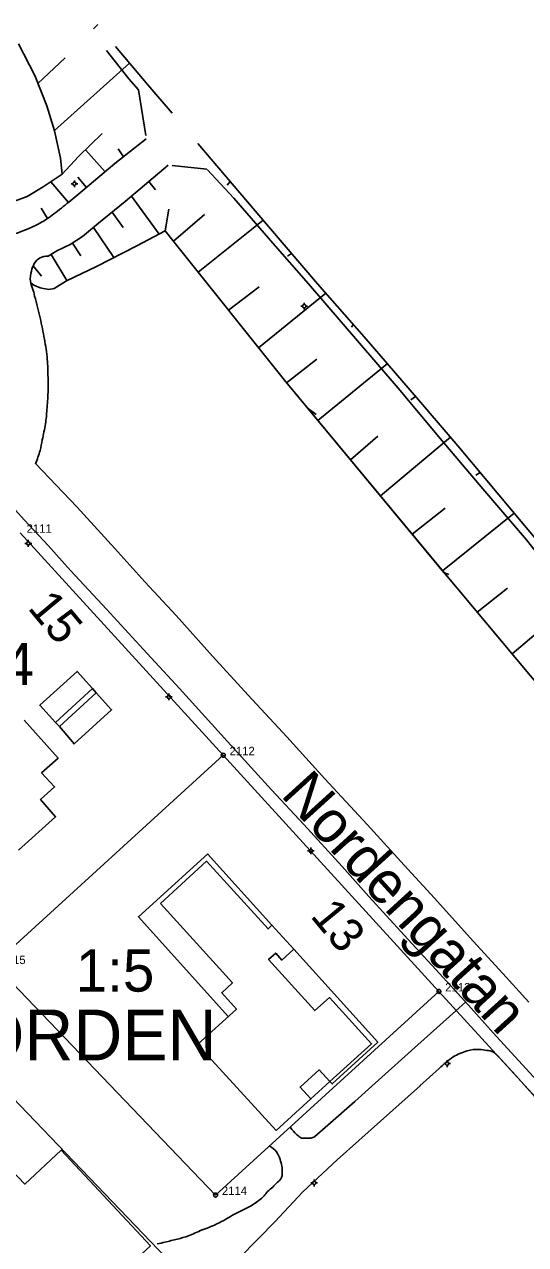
# Model space of a CAD drawing. Extents: x 1517693 to 1518189, y 6494860 to 6495280.
# Drawn here: x 1518024.6 to 1518083.9, y 6495135.7 to 6495280.1 of the extents above; entities that cross this region are included whole.
import ezdxf

# ---------------------------------------------------------------- set-up
doc = ezdxf.new("R2010")
doc.units = 0
for name, color, linetype in [('adress', 7, 'Continuous'), ('bostadshus', 7, 'Continuous'), ('fastighetsbeteckning', 7, 'Continuous'), ('gatunamn', 7, 'Continuous'), ('gc_vag', 7, 'Continuous'), ('grans', 7, 'Continuous'), ('granspunkt', 7, 'Continuous'), ('granspunkt_text', 7, 'Continuous'), ('kvartersgrans', 7, 'Continuous'), ('kvartersgrans_utan_fastgr', 7, 'Continuous'), ('kvartersnamn', 7, 'Continuous'), ('skarmtak', 7, 'Continuous'), ('slant_skraffering', 7, 'Continuous'), ('slantfot', 7, 'Continuous'), ('slantkron', 7, 'Continuous'), ('staket', 7, 'Continuous'), ('stenmur', 7, 'Continuous'), ('stolpe_belysning', 7, 'Continuous'), ('vagkant', 7, 'Continuous')]:
    doc.layers.add(name, color=color, linetype=linetype)

msp = doc.modelspace()

# ---------------------------------------------------------------- linework, layer by layer
at = {"layer": 'bostadshus'}
for points in [[(1518024.6, 6495197.78), (1518028.63, 6495193.3), (1518026.66, 6495191.54), (1518028.19, 6495189.89), (1518026.54, 6495188.39), (1518028.31, 6495186.35), (1518023.92, 6495182.41)], [(1518040.73, 6495176.09), (1518046.15, 6495181.08), (1518053.45, 6495173.08), (1518053.89, 6495173.53), (1518056.49, 6495170.67), (1518055.05, 6495169.4), (1518054.35, 6495170.23), (1518053.49, 6495169.48), (1518058.96, 6495163.41), (1518060.7, 6495164.96), (1518065.68, 6495159.49), (1518060.76, 6495155.03), (1518059.49, 6495156.39), (1518057.23, 6495154.36), (1518058.51, 6495152.97), (1518054.38, 6495149.24), (1518045.11, 6495159.41), (1518049.7, 6495163.58), (1518047.96, 6495165.53), (1518049.23, 6495166.71), (1518040.73, 6495176.09)], [(1518010.24, 6495136.01), (1518021.49, 6495146.21), (1518024.66, 6495142.89), (1518028.99, 6495146.91), (1518039.53, 6495135.57), (1518028.29, 6495125.18), (1518029.76, 6495123.58), (1518022.02, 6495116.58), (1518022.18, 6495116.39), (1518018.47, 6495113.08), (1518013.52, 6495118.58), (1518022.53, 6495126.88), (1518015.48, 6495134.51), (1518013.35, 6495132.59), (1518010.23, 6495136.01)]]:
    msp.add_lwpolyline(points, dxfattribs=at)
at = {"layer": 'gc_vag'}
msp.add_line((1518071.39, 6495154.52), (1518073.68, 6495156.57), dxfattribs=at)
for points in [[(1518039.04, 6495266.56), (1518035.33, 6495263.64), (1518031.54, 6495260.45), (1518029.88, 6495259.08)], [(1518041.63, 6495263.45), (1518036.56, 6495259.17), (1518033.37, 6495256.57), (1518031.5, 6495255), (1518030.05, 6495254.06), (1518028.48, 6495253.3), (1518027.42, 6495252.7)], [(1518076.79, 6495164.43), (1518075.63, 6495163.38), (1518070.4, 6495158.71), (1518065.72, 6495154.49), (1518063.7, 6495152.67)], [(1518080.55, 6495158.09), (1518082.73, 6495155.72), (1518085.02, 6495153.19)], [(1518054.23, 6495138.43), (1518057.55, 6495141.96), (1518061.62, 6495145.76), (1518066.75, 6495150.35), (1518071.45, 6495154.57)], [(1518063.7, 6495152.67), (1518060.52, 6495149.87), (1518058.98, 6495148.51)], [(1518041.89, 6495125.55), (1518041.87, 6495125.6), (1518046.09, 6495130.04), (1518050.01, 6495134.11), (1518054.38, 6495138.58)]]:
    msp.add_lwpolyline(points, dxfattribs=at)
for points in [[(1518029.88, 6495259.08), (1518028.1, 6495257.68), (1518026.44, 6495256.57), (1518024.36, 6495255.64), (1518021.93, 6495254.91), (1518019.81, 6495254.79), (1518018.36, 6495254.91), (1518017.25, 6495255.21), (1518015.42, 6495255.89), (1518013.77, 6495256.74), (1518011.51, 6495257.93), (1518010.15, 6495259.08)], [(1518027.42, 6495252.7), (1518026.48, 6495252.49), (1518025.8, 6495251.81), (1518025.46, 6495250.91), (1518025.33, 6495249.72), (1518025.59, 6495248.87), (1518025.84, 6495247.94)], [(1518025.84, 6495247.94), (1518026.48, 6495245.38), (1518026.99, 6495242.87), (1518027.33, 6495240.49), (1518027.42, 6495238.32), (1518027.42, 6495236.58), (1518027.29, 6495234.53), (1518027.12, 6495232.83), (1518026.74, 6495230.96), (1518026.48, 6495229.68), (1518025.93, 6495228.11)], [(1518073.68, 6495156.57), (1518075.34, 6495157.93), (1518076.97, 6495158.65), (1518078.39, 6495158.83), (1518079.32, 6495158.71), (1518080.08, 6495158.5), (1518080.56, 6495158.08)], [(1518058.98, 6495148.51), (1518058.5, 6495148.33), (1518057.83, 6495148.33), (1518057.38, 6495148.33), (1518057.2, 6495148.45), (1518056.81, 6495148.75), (1518056.08, 6495149.57)], [(1518053.66, 6495147.39), (1518054.44, 6495146.7), (1518054.86, 6495145.8), (1518055.07, 6495145.01), (1518055.1, 6495144.2), (1518055.04, 6495143.65), (1518054.56, 6495143.11), (1518053.99, 6495142.54), (1518053.38, 6495141.99), (1518052.96, 6495141.48), (1518052.39, 6495140.97), (1518051.73, 6495140.51), (1518050.49, 6495139.85), (1518049.25, 6495139.19), (1518047.11, 6495138.04), (1518045.33, 6495137.35)], [(1518045.64, 6495137.47), (1518044.02, 6495136.77), (1518042.72, 6495136.38), (1518041.25, 6495136.02), (1518040.34, 6495135.81)]]:
    msp.add_spline(points, degree=3, dxfattribs=at)
at = {"layer": 'grans'}
for p, q in [((1518024.14, 6495219.95), (1518048.14, 6495193.63)), ((1518048.14, 6495193.63), (1518021.05, 6495168.92)), ((1518073.64, 6495165.68), (1518048.14, 6495193.63)), ((1518021.05, 6495168.92), (1518047.23, 6495141.59)), ((1518047.23, 6495141.59), (1518073.64, 6495165.68)), ((1518041.37, 6495134.15), (1518015.43, 6495161.24))]:
    msp.add_line(p, q, dxfattribs=at)
at = {"layer": 'granspunkt'}
for centre in [(1518048.14, 6495193.63), (1518073.64, 6495165.68), (1518047.23, 6495141.59)]:
    msp.add_circle(centre, 0.237, dxfattribs=at)
at = {"layer": 'kvartersgrans'}
msp.add_lwpolyline([(1518024.14, 6495219.95), (1518048.14, 6495193.63), (1518073.64, 6495165.68)], dxfattribs=at)
at = {"layer": 'kvartersgrans_utan_fastgr'}
msp.add_line((1518073.64, 6495165.68), (1518099.97, 6495136.82), dxfattribs=at)
at = {"layer": 'skarmtak'}
for p, q in [((1518046.29, 6495181.97), (1518053.9, 6495173.52)), ((1518060.76, 6495155.04), (1518058.51, 6495152.98))]:
    msp.add_line(p, q, dxfattribs=at)
for points in [[(1518032.66, 6495201.51), (1518030.87, 6495203.55), (1518026.44, 6495199.54), (1518028.31, 6495197.52)], [(1518033.12, 6495201.01), (1518034.94, 6495199.02), (1518030.51, 6495194.97), (1518028.77, 6495197.02)], [(1518048.74, 6495162.7), (1518038.11, 6495174.52), (1518046.3, 6495181.97)], [(1518056.49, 6495170.68), (1518066.41, 6495159.66), (1518061.02, 6495154.73), (1518060.76, 6495155.03)]]:
    msp.add_lwpolyline(points, dxfattribs=at)
at = {"layer": 'slant_skraffering'}
for p, q in [((1518033.3, 6495280.11), (1518032.79, 6495279.6)), ((1518026.23, 6495273.12), (1518029.43, 6495276.17)), ((1518028.19, 6495267.54), (1518037.05, 6495275.53)), ((1518034.17, 6495262.66), (1518031.86, 6495265.28)), ((1518036.35, 6495264.44), (1518035.7, 6495265.38)), ((1518029.83, 6495259.04), (1518027.77, 6495261.49)), ((1518031.95, 6495260.79), (1518030.96, 6495262.02)), ((1518039.35, 6495261.53), (1518040.11, 6495260.53)), ((1518048.97, 6495261.51), (1518048.61, 6495261.08)), ((1518037.29, 6495259.79), (1518040.57, 6495255.3)), ((1518027.35, 6495257.14), (1518026.59, 6495258.38)), ((1518034.99, 6495257.89), (1518036.32, 6495256.08)), ((1518042.26, 6495254.44), (1518045.94, 6495257.6)), ((1518045.17, 6495250.8), (1518052.87, 6495256.95)), ((1518032.79, 6495256.08), (1518035.22, 6495252.52)), ((1518030.33, 6495254.24), (1518031.29, 6495252.73)), ((1518027.78, 6495252.9), (1518029.63, 6495249.79)), ((1518056.22, 6495253.01), (1518055.75, 6495252.7)), ((1518025.66, 6495251.54), (1518026.63, 6495250.32)), ((1518048.75, 6495246.29), (1518052.4, 6495249.06)), ((1518052.31, 6495241.83), (1518060.26, 6495248.29)), ((1518063.49, 6495244.61), (1518063.3, 6495244.27)), ((1518055.6, 6495237.7), (1518059.22, 6495240.5)), ((1518059.31, 6495233.23), (1518067.52, 6495239.96)), ((1518070.86, 6495236.08), (1518070.32, 6495235.7)), ((1518058.07, 6495234.72), (1518059.14, 6495233.93)), ((1518063.19, 6495228.57), (1518066.41, 6495231.37)), ((1518066.72, 6495224.32), (1518075, 6495231.26)), ((1518078.5, 6495227.09), (1518078.01, 6495226.76)), ((1518070.48, 6495219.79), (1518074.39, 6495222.87)), ((1518074.07, 6495215.46), (1518082.52, 6495222.28)), ((1518078.17, 6495210.56), (1518081.75, 6495213.39)), ((1518082.3, 6495205.63), (1518090.55, 6495212.65))]:
    msp.add_line(p, q, dxfattribs=at)
at = {"layer": 'slantfot'}
msp.add_line((1518042.1, 6495263.42), (1518046.2, 6495262.98), dxfattribs=at)
for points in [[(1518034.33, 6495277), (1518036.96, 6495273.68), (1518038.11, 6495272.36), (1518038.98, 6495266.98)], [(1518033.82, 6495267.18), (1518031.03, 6495264.49), (1518029.1, 6495262.4), (1518026.86, 6495260.87), (1518024.95, 6495259.76), (1518022.7, 6495258.91), (1518020.4, 6495258.19), (1518018.78, 6495257.89), (1518016.87, 6495257.85), (1518014.79, 6495258.02), (1518013.81, 6495258.19), (1518012.07, 6495258.7), (1518010.7, 6495259.21), (1518007.15, 6495261.25)], [(1518058.2, 6495249.4), (1518054, 6495254.22), (1518049.39, 6495259.54), (1518046.23, 6495262.95)], [(1518041.71, 6495258.26), (1518041.28, 6495255.68), (1518037.92, 6495253.89), (1518033.16, 6495251.47), (1518029.59, 6495249.77), (1518028.14, 6495248.87), (1518027.5, 6495248.75), (1518026.48, 6495248.92), (1518025.76, 6495249.26), (1518025.41, 6495249.47)], [(1518074.04, 6495230.84), (1518068.84, 6495237.08), (1518064.02, 6495242.66), (1518058.2, 6495249.4)], [(1518092.27, 6495208.77), (1518088.68, 6495213.17), (1518084, 6495219.13), (1518078.82, 6495225.16), (1518074.04, 6495230.84)]]:
    msp.add_lwpolyline(points, dxfattribs=at)
at = {"layer": 'slantkron'}
msp.add_lwpolyline([(1518023.91, 6495277.8), (1518025.86, 6495274.06), (1518027.27, 6495270.49), (1518028.2, 6495267.51), (1518028.88, 6495264.27), (1518029.1, 6495262.4)], dxfattribs=at)
at = {"layer": 'staket'}
for q in [(1518074.17, 6495215.34), (1518074.7, 6495214.71)]:
    msp.add_line((1518055.52, 6495237.8), q, dxfattribs=at)
for points in [[(1518041.26, 6495255.67), (1518042.34, 6495254.35), (1518055.52, 6495237.8)], [(1518055.52, 6495237.8), (1518074.24, 6495215.26), (1518074.24, 6495215.26), (1518074.83, 6495215.01)], [(1518074.17, 6495215.34), (1518084.47, 6495203.04), (1518092.38, 6495193.53)]]:
    msp.add_lwpolyline(points, dxfattribs=at)
at = {"layer": 'stenmur'}
for p, q in [((1518028.31, 6495197.52), (1518032.66, 6495201.51)), ((1518028.77, 6495197.02), (1518033.12, 6495201.01)), ((1518032.66, 6495201.51), (1518033.12, 6495201.01)), ((1518028.31, 6495197.52), (1518028.77, 6495197.02))]:
    msp.add_line(p, q, dxfattribs=at)
at = {"layer": 'stolpe_belysning'}
for p, q in [((1518030.34, 6495261.25), (1518030.14, 6495261.25)), ((1518030.54, 6495261.45), (1518030.54, 6495261.65)), ((1518030.74, 6495261.25), (1518030.94, 6495261.25)), ((1518030.54, 6495261.05), (1518030.54, 6495260.85)), ((1518057.52, 6495246.77), (1518057.32, 6495246.77)), ((1518057.72, 6495246.97), (1518057.72, 6495247.17)), ((1518057.92, 6495246.77), (1518058.12, 6495246.77)), ((1518057.72, 6495246.57), (1518057.72, 6495246.37)), ((1518024.89, 6495218.7), (1518024.69, 6495218.7)), ((1518025.09, 6495218.9), (1518025.09, 6495219.1)), ((1518025.09, 6495218.5), (1518025.09, 6495218.3)), ((1518025.29, 6495218.7), (1518025.49, 6495218.7)), ((1518041.51, 6495200.53), (1518041.31, 6495200.53)), ((1518041.71, 6495200.73), (1518041.71, 6495200.93)), ((1518041.91, 6495200.53), (1518042.11, 6495200.53)), ((1518041.71, 6495200.33), (1518041.71, 6495200.13)), ((1518058.3, 6495182.31), (1518058.1, 6495182.31)), ((1518058.5, 6495182.51), (1518058.5, 6495182.71)), ((1518058.5, 6495182.11), (1518058.5, 6495181.91)), ((1518058.7, 6495182.31), (1518058.9, 6495182.31)), ((1518074.61, 6495157.34), (1518074.61, 6495157.54)), ((1518074.41, 6495157.14), (1518074.21, 6495157.14)), ((1518074.61, 6495156.94), (1518074.61, 6495156.74)), ((1518074.81, 6495157.14), (1518075.01, 6495157.14)), ((1518058.7, 6495143.02), (1518058.5, 6495143.02)), ((1518058.9, 6495143.22), (1518058.9, 6495143.42)), ((1518058.9, 6495142.82), (1518058.9, 6495142.62)), ((1518059.1, 6495143.02), (1518059.3, 6495143.02))]:
    msp.add_line(p, q, dxfattribs=at)
for centre in [(1518030.54, 6495261.25), (1518057.72, 6495246.77), (1518025.09, 6495218.7), (1518041.71, 6495200.53), (1518058.5, 6495182.31), (1518074.61, 6495157.14), (1518058.9, 6495143.02)]:
    msp.add_circle(centre, 0.2, dxfattribs=at)
at = {"layer": 'vagkant'}
for points in [[(1518035.39, 6495277.51), (1518039.22, 6495272.95), (1518042.09, 6495269.61)], [(1518059.3, 6495249.4), (1518053.5, 6495256.21), (1518045.13, 6495266)], [(1518075.88, 6495230.24), (1518071.22, 6495235.67), (1518064.8, 6495243.12), (1518059.3, 6495249.4)], [(1518094.04, 6495208.38), (1518088.29, 6495215.41), (1518082.34, 6495222.5), (1518075.88, 6495230.24)], [(1518025.94, 6495228.14), (1518030.83, 6495223.01), (1518035.32, 6495218.1), (1518038.86, 6495214.16), (1518042.56, 6495210.16)], [(1518019.86, 6495226.68), (1518024.65, 6495221.44), (1518027.44, 6495218.44), (1518030.07, 6495215.49), (1518034.35, 6495210.92)], [(1518034.35, 6495210.92), (1518038.68, 6495206.19), (1518042.95, 6495201.52), (1518048.65, 6495195.27)], [(1518042.56, 6495210.16), (1518046.86, 6495205.34), (1518051.08, 6495200.73), (1518055.65, 6495195.82)], [(1518048.65, 6495195.27), (1518053.86, 6495189.54), (1518057.65, 6495185.42), (1518062.2, 6495180.45)], [(1518055.65, 6495195.82), (1518060.17, 6495190.85), (1518065.14, 6495185.45), (1518069.53, 6495180.63)], [(1518062.2, 6495180.45), (1518065.35, 6495176.93), (1518069.53, 6495172.35), (1518073.26, 6495168.26), (1518077.08, 6495164.11)], [(1518069.53, 6495180.63), (1518073.11, 6495176.72), (1518077.69, 6495171.65), (1518081.2, 6495167.8), (1518084.26, 6495164.41)], [(1518077.08, 6495164.11), (1518080.05, 6495160.8), (1518085.2, 6495155.13), (1518088.32, 6495151.7), (1518091.63, 6495148.01)]]:
    msp.add_lwpolyline(points, dxfattribs=at)

# ---------------------------------------------------------------- texts
at = {"layer": 'adress'}
for s, rotation, p in [('15', 309.7861, (1518024.92, 6495211.03)), ('13', 309.455, (1518058.34, 6495174.58))]:
    msp.add_text(s, height=4, rotation=rotation, dxfattribs=at).set_placement(p)
at = {"layer": 'fastighetsbeteckning'}
for s, p in [('1:4', (1518016.48, 6495201.93)), ('1:5', (1518030.7, 6495165.66))]:
    msp.add_text(s, height=5, rotation=0.0021, dxfattribs=at).set_placement(p)
at = {"layer": 'gatunamn'}
msp.add_text('Nordengatan', height=5, rotation=312.3013, dxfattribs=at).set_placement((1518054.82, 6495188.88))
at = {"layer": 'granspunkt_text'}
for s, p in [('2111', (1518024.89, 6495219.95)), ('2112', (1518048.89, 6495193.63)), ('2115', (1518021.8, 6495168.92)), ('2113', (1518074.39, 6495165.68)), ('2114', (1518047.98, 6495141.59))]:
    msp.add_text(s, height=1, dxfattribs=at).set_placement(p)
at = {"layer": 'kvartersnamn'}
msp.add_text('NORDEN', height=6, rotation=0.0021, dxfattribs=at).set_placement((1518012.58, 6495157.53))

doc.saveas('drawing.dxf')
